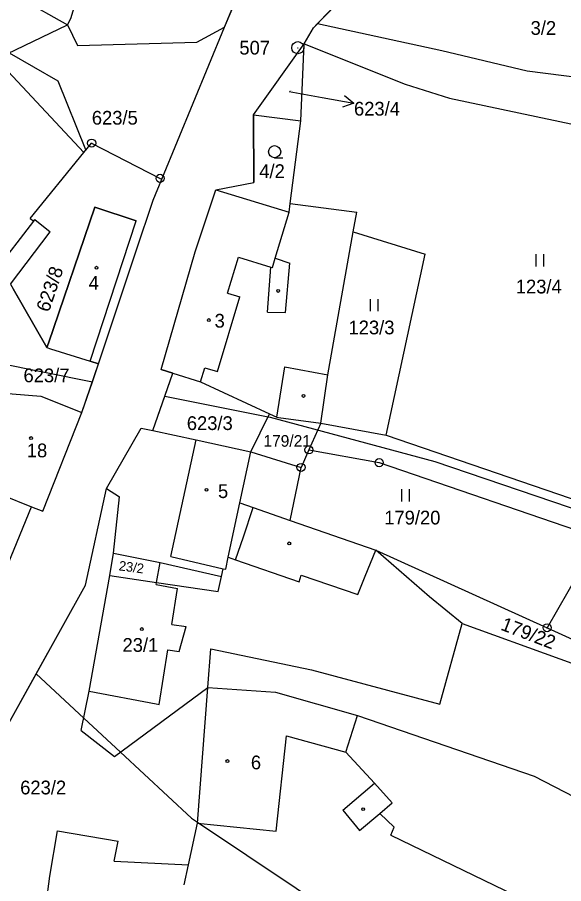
# Model space of a CAD drawing. Extents: x -743888 to -742027, y -1128394 to -1126768.
# Drawn here: x -742886 to -742818.4, y -1127432.2 to -1127325 of the extents above; entities that cross this region are included whole.
import ezdxf

# ---------------------------------------------------------------- set-up
doc = ezdxf.new("R2010")
doc.units = 0
for name, color, linetype in [('Vrstva 1', 7, 'Continuous'), ('Vrstva 16', 7, 'Continuous'), ('Vrstva 17', 7, 'Continuous'), ('Vrstva 18', 7, 'Continuous'), ('Vrstva 19', 7, 'Continuous'), ('Vrstva 24', 7, 'Continuous'), ('Vrstva 25', 7, 'Continuous'), ('Vrstva 3', 7, 'Continuous'), ('Vrstva 37', 7, 'Continuous'), ('Vrstva 4', 7, 'Continuous'), ('Vrstva 52', 7, 'Continuous'), ('Vrstva 6', 7, 'Continuous')]:
    doc.layers.add(name, color=color, linetype=linetype)

msp = doc.modelspace()

# ---------------------------------------------------------------- linework, layer by layer
at = {"layer": 'Vrstva 1'}
for points in [[(-742879.39, -1127325.18), (-742872.07, -1127300.81)], [(-742849.32, -1127326.31), (-742829.22, -1127305.6)], [(-742885.51, -1127322.69), (-742879.78, -1127325.96)], [(-742860.36, -1127326.22), (-742858.83, -1127322.61)], [(-742879.78, -1127325.96), (-742879.39, -1127325.18)], [(-742868.13, -1127345.05), (-742860.36, -1127326.22)], [(-742850.51, -1127328.29), (-742849.32, -1127326.31)], [(-742856.76, -1127337.08), (-742850.51, -1127328.29)], [(-742850.89, -1127337.85), (-742850.51, -1127328.29)], [(-742850.51, -1127328.29), (-742837.98, -1127333.31)], [(-742887.13, -1127331.73), (-742877.76, -1127341.76)], [(-742837.98, -1127333.31), (-742832.48, -1127335.04)], [(-742832.48, -1127335.04), (-742808.12, -1127340.19)], [(-742856.76, -1127337.08), (-742850.89, -1127337.85)], [(-742852.21, -1127348.07), (-742850.89, -1127337.85)], [(-742877.76, -1127341.76), (-742876.8, -1127340.59)], [(-742876.8, -1127340.59), (-742868.33, -1127344.95)], [(-742884.41, -1127349.91), (-742877.76, -1127341.76)], [(-742868.33, -1127344.95), (-742868.13, -1127345.05)], [(-742869.2, -1127347.63), (-742868.13, -1127345.05)], [(-742863.97, -1127354.06), (-742861.43, -1127346.38)], [(-742861.43, -1127346.38), (-742852.34, -1127349.14)], [(-742870.17, -1127350.6), (-742869.2, -1127347.63)], [(-742852.34, -1127349.14), (-742852.21, -1127348.07)], [(-742882.16, -1127365.36), (-742876.42, -1127348.52)], [(-742876.42, -1127348.52), (-742871.31, -1127350.22)], [(-742844.41, -1127351.58), (-742843.97, -1127349.15)], [(-742888.82, -1127356.51), (-742883.97, -1127350.26)], [(-742884.41, -1127349.91), (-742883.97, -1127350.26)], [(-742876.98, -1127367.59), (-742871.31, -1127350.22)], [(-742875.94, -1127367.92), (-742870.28, -1127350.94)], [(-742870.28, -1127350.94), (-742870.17, -1127350.6)], [(-742844.41, -1127351.58), (-742835.5, -1127354.31)], [(-742868.2, -1127368.62), (-742863.97, -1127354.06)], [(-742840.33, -1127376.73), (-742835.5, -1127354.31)], [(-742886.85, -1127358.03), (-742882.34, -1127365.88)], [(-742882.34, -1127365.88), (-742882.16, -1127365.36)], [(-742882.34, -1127365.88), (-742881.88, -1127366.03)], [(-742881.88, -1127366.03), (-742876.98, -1127367.59)], [(-742878.02, -1127373.93), (-742875.94, -1127367.92)], [(-742876.98, -1127367.59), (-742875.94, -1127367.92)], [(-742868.2, -1127368.62), (-742866.77, -1127369.06)], [(-742866.77, -1127369.06), (-742863.32, -1127370.11)], [(-742848.44, -1127375.26), (-742847.58, -1127369.27)], [(-742890.23, -1127371.33), (-742883.09, -1127371.9)], [(-742883.09, -1127371.9), (-742878.02, -1127373.93)], [(-742882.85, -1127386.15), (-742878.02, -1127373.93)], [(-742853.88, -1127374.51), (-742853.68, -1127374.54)], [(-742853.68, -1127374.54), (-742848.44, -1127375.26)], [(-742874.95, -1127383.34), (-742870.69, -1127375.86)], [(-742848.44, -1127375.26), (-742849.91, -1127378.55)], [(-742848.44, -1127375.26), (-742840.33, -1127376.73)], [(-742840.33, -1127376.73), (-742809.96, -1127387.12)], [(-742863.88, -1127377.32), (-742857.08, -1127378.78)], [(-742849.91, -1127378.55), (-742850.88, -1127380.72)], [(-742849.91, -1127378.55), (-742841.21, -1127380.13), (-742814.03, -1127389.43), (-742820.42, -1127400.56)], [(-742877.58, -1127395.3), (-742874.95, -1127383.34)], [(-742887.91, -1127384.11), (-742884.23, -1127385.59)], [(-742884.23, -1127385.59), (-742882.85, -1127386.15)], [(-742858.02, -1127389.32), (-742856.8, -1127385.69)], [(-742856.8, -1127385.69), (-742852.24, -1127387.27)], [(-742852.24, -1127387.27), (-742841.62, -1127390.96)], [(-742858.98, -1127392.15), (-742858.02, -1127389.32)], [(-742841.62, -1127390.96), (-742820.42, -1127400.56)], [(-742874.57, -1127394.1), (-742874.08, -1127391.34)], [(-742874.08, -1127391.34), (-742868.32, -1127392.49)], [(-742860.2, -1127393.33), (-742859.88, -1127391.84)], [(-742859.88, -1127391.84), (-742858.98, -1127392.15)], [(-742868.32, -1127392.49), (-742860.73, -1127394.22)], [(-742860.73, -1127394.22), (-742860.51, -1127393.26)], [(-742860.51, -1127393.26), (-742860.2, -1127393.33)], [(-742877.11, -1127408.41), (-742874.57, -1127394.1)], [(-742891.64, -1127420.53), (-742877.58, -1127395.3)], [(-742820.42, -1127400.56), (-742810.86, -1127404.89)], [(-742863.7, -1127424.73), (-742862.41, -1127407.96)], [(-742862.41, -1127407.96), (-742854.05, -1127408.52)], [(-742878.08, -1127413.29), (-742877.11, -1127408.41)], [(-742854.05, -1127408.52), (-742843.9, -1127411.41)], [(-742845.34, -1127415.94), (-742843.9, -1127411.41)], [(-742843.9, -1127411.41), (-742822, -1127418.91)], [(-742845.34, -1127415.94), (-742841.79, -1127419.79)], [(-742822, -1127418.91), (-742793.34, -1127433.72)], [(-742841.79, -1127419.79), (-742839.58, -1127422.24)], [(-742841.12, -1127423.54), (-742839.58, -1127422.24)], [(-742841.12, -1127423.54), (-742839.33, -1127425.23)], [(-742864.82, -1127429.91), (-742863.7, -1127424.73)], [(-742839.78, -1127426.23), (-742839.33, -1127425.23)], [(-742839.78, -1127426.23), (-742821.85, -1127434.87)], [(-742865.34, -1127432.36), (-742864.82, -1127429.91)]]:
    msp.add_lwpolyline(points, dxfattribs=at)
at = {"layer": 'Vrstva 16'}
msp.add_line((-742845.48, -1127334.69), (-742844.33, -1127335.66), dxfattribs=at)
for points in [[(-742852.36, -1127334.2), (-742848.27, -1127334.94)], [(-742848.27, -1127334.94), (-742844.33, -1127335.66), (-742845.75, -1127336.16)]]:
    msp.add_lwpolyline(points, dxfattribs=at)
at = {"layer": 'Vrstva 24'}
for p, q in [((-742851.33, -1127328.78), (-742851.23, -1127328.78)), ((-742876.85, -1127340.59), (-742876.75, -1127340.59)), ((-742868.38, -1127344.95), (-742868.28, -1127344.95)), ((-742849.96, -1127378.55), (-742849.86, -1127378.55)), ((-742841.26, -1127380.13), (-742841.16, -1127380.13)), ((-742850.93, -1127380.72), (-742850.83, -1127380.72)), ((-742820.47, -1127400.56), (-742820.37, -1127400.56))]:
    msp.add_line(p, q, dxfattribs=at)
for centre, radius in [((-742851.28, -1127328.78), 0.756), ((-742876.8, -1127340.59), 0.499), ((-742868.33, -1127344.95), 0.499), ((-742849.91, -1127378.55), 0.499), ((-742850.88, -1127380.72), 0.499), ((-742841.21, -1127380.13), 0.499), ((-742820.42, -1127400.56), 0.499)]:
    msp.add_circle(centre, radius, dxfattribs=at)
at = {"layer": 'Vrstva 25'}
for p, q in [((-742854.15, -1127342.4), (-742853.15, -1127342.4)), ((-742821.81, -1127354.35), (-742821.81, -1127355.85)), ((-742820.81, -1127355.85), (-742820.81, -1127354.35)), ((-742842.33, -1127359.88), (-742842.33, -1127361.38)), ((-742841.33, -1127361.38), (-742841.33, -1127359.88)), ((-742838.45, -1127383.42), (-742838.45, -1127384.92)), ((-742837.45, -1127384.92), (-742837.45, -1127383.42))]:
    msp.add_line(p, q, dxfattribs=at)
for centre, radius in [((-742854.15, -1127341.65), 0.75), ((-742876.21, -1127356.01), 0.175), ((-742853.7, -1127358.88), 0.175), ((-742862.29, -1127362.48), 0.175), ((-742850.57, -1127371.88), 0.175), ((-742884.31, -1127377.08), 0.175), ((-742862.59, -1127383.49), 0.175), ((-742852.33, -1127390.12), 0.175), ((-742870.58, -1127400.72), 0.175), ((-742860, -1127417.05), 0.175), ((-742843.18, -1127423), 0.175)]:
    msp.add_circle(centre, radius, dxfattribs=at)
at = {"layer": 'Vrstva 3'}
for points in [[(-742863.97, -1127354.06), (-742861.43, -1127346.38)], [(-742861.43, -1127346.38), (-742852.34, -1127349.14)], [(-742882.16, -1127365.36), (-742876.42, -1127348.52)], [(-742876.42, -1127348.52), (-742871.31, -1127350.22)], [(-742854.07, -1127354.83), (-742852.34, -1127349.14)], [(-742876.98, -1127367.59), (-742871.31, -1127350.22)], [(-742868.2, -1127368.62), (-742863.97, -1127354.06)], [(-742859.99, -1127359.17), (-742858.64, -1127354.7)], [(-742858.64, -1127354.7), (-742854.62, -1127355.93)], [(-742854.43, -1127355.98), (-742854.07, -1127354.83)], [(-742854.62, -1127355.93), (-742854.43, -1127355.98)], [(-742861.21, -1127368.86), (-742858.46, -1127359.63)], [(-742859.99, -1127359.17), (-742858.46, -1127359.63)], [(-742882.34, -1127365.88), (-742882.16, -1127365.36)], [(-742882.34, -1127365.88), (-742881.88, -1127366.03)], [(-742881.88, -1127366.03), (-742876.98, -1127367.59)], [(-742868.2, -1127368.62), (-742866.77, -1127369.06)], [(-742863.32, -1127370.11), (-742862.8, -1127368.38)], [(-742862.8, -1127368.38), (-742861.21, -1127368.86)], [(-742866.77, -1127369.06), (-742863.32, -1127370.11)], [(-742890.23, -1127371.33), (-742883.09, -1127371.9)], [(-742883.09, -1127371.9), (-742878.02, -1127373.93)], [(-742882.85, -1127386.15), (-742878.02, -1127373.93)], [(-742866.98, -1127391.74), (-742863.88, -1127377.32)], [(-742863.88, -1127377.32), (-742857.08, -1127378.78)], [(-742858.47, -1127385.11), (-742857.08, -1127378.78)], [(-742887.91, -1127384.11), (-742884.23, -1127385.59)], [(-742884.23, -1127385.59), (-742882.85, -1127386.15)], [(-742859.88, -1127391.84), (-742858.47, -1127385.11)], [(-742866.98, -1127391.74), (-742860.51, -1127393.26)], [(-742860.2, -1127393.33), (-742859.88, -1127391.84)], [(-742860.51, -1127393.26), (-742860.2, -1127393.33)], [(-742877.11, -1127408.41), (-742874.57, -1127394.1)], [(-742874.57, -1127394.1), (-742868.78, -1127394.95)], [(-742868.83, -1127395.2), (-742868.78, -1127394.95)], [(-742868.83, -1127395.2), (-742866.18, -1127395.7)], [(-742866.88, -1127400.14), (-742866.18, -1127395.7)], [(-742866.88, -1127400.14), (-742865.1, -1127400.42)], [(-742865.98, -1127403.51), (-742865.1, -1127400.42)], [(-742868.44, -1127410.04), (-742867.38, -1127403.29)], [(-742867.38, -1127403.29), (-742865.98, -1127403.51)], [(-742863.7, -1127424.73), (-742862.41, -1127407.96)], [(-742862.41, -1127407.96), (-742854.05, -1127408.52)], [(-742877.11, -1127408.41), (-742868.83, -1127409.96)], [(-742854.05, -1127408.52), (-742843.9, -1127411.41)], [(-742868.83, -1127409.96), (-742868.44, -1127410.04)], [(-742845.34, -1127415.94), (-742843.9, -1127411.41)], [(-742853.96, -1127425.75), (-742852.67, -1127413.92)], [(-742852.67, -1127413.92), (-742845.34, -1127415.94)], [(-742863.7, -1127424.73), (-742853.96, -1127425.75)]]:
    msp.add_lwpolyline(points, dxfattribs=at)
at = {"layer": 'Vrstva 37'}
for centre in [(-742876.21, -1127356.01), (-742862.29, -1127362.48), (-742884.31, -1127377.08), (-742862.59, -1127383.49), (-742870.58, -1127400.72), (-742860, -1127417.05)]:
    msp.add_circle(centre, 0.175, dxfattribs=at)
at = {"layer": 'Vrstva 4'}
for points in [[(-742854.07, -1127354.83), (-742852.34, -1127349.14)], [(-742883.97, -1127350.26), (-742883.82, -1127350.06)], [(-742883.82, -1127350.06), (-742881.92, -1127351.58)], [(-742886.85, -1127358.03), (-742881.92, -1127351.58)], [(-742859.99, -1127359.17), (-742858.64, -1127354.7)], [(-742858.64, -1127354.7), (-742854.62, -1127355.93)], [(-742854.43, -1127355.98), (-742854.07, -1127354.83)], [(-742854.07, -1127354.83), (-742852.28, -1127355.43)], [(-742852.82, -1127361.54), (-742852.28, -1127355.43)], [(-742855.05, -1127361.49), (-742854.62, -1127355.93)], [(-742854.62, -1127355.93), (-742854.43, -1127355.98)], [(-742861.21, -1127368.86), (-742858.46, -1127359.63)], [(-742859.99, -1127359.17), (-742858.46, -1127359.63)], [(-742855.05, -1127361.49), (-742852.82, -1127361.54)], [(-742863.32, -1127370.11), (-742862.8, -1127368.38)], [(-742862.8, -1127368.38), (-742861.21, -1127368.86)], [(-742853.88, -1127374.51), (-742852.88, -1127368.29)], [(-742852.88, -1127368.29), (-742847.58, -1127369.27)], [(-742866.98, -1127391.74), (-742863.88, -1127377.32)], [(-742858.47, -1127385.11), (-742857.08, -1127378.78)], [(-742859.88, -1127391.84), (-742858.47, -1127385.11)], [(-742858.47, -1127385.11), (-742856.8, -1127385.69)], [(-742842.93, -1127394.18), (-742841.62, -1127390.96)], [(-742866.98, -1127391.74), (-742860.51, -1127393.26)], [(-742858.98, -1127392.15), (-742851.13, -1127394.86), (-742850.85, -1127394.06), (-742843.86, -1127396.45), (-742842.93, -1127394.18)], [(-742868.78, -1127394.95), (-742868.32, -1127392.49)], [(-742868.83, -1127395.2), (-742868.78, -1127394.95)], [(-742868.83, -1127395.2), (-742866.18, -1127395.7)], [(-742866.88, -1127400.14), (-742866.18, -1127395.7)], [(-742866.88, -1127400.14), (-742865.1, -1127400.42)], [(-742865.98, -1127403.51), (-742865.1, -1127400.42)], [(-742868.44, -1127410.04), (-742867.38, -1127403.29)], [(-742867.38, -1127403.29), (-742865.98, -1127403.51)], [(-742877.11, -1127408.41), (-742868.83, -1127409.96)], [(-742868.83, -1127409.96), (-742868.44, -1127410.04)], [(-742853.96, -1127425.75), (-742852.67, -1127413.92)], [(-742852.67, -1127413.92), (-742845.34, -1127415.94)], [(-742845.71, -1127423.13), (-742841.79, -1127419.79)], [(-742845.71, -1127423.13), (-742843.66, -1127425.67)], [(-742843.66, -1127425.67), (-742841.12, -1127423.54)], [(-742863.7, -1127424.73), (-742853.96, -1127425.75)]]:
    msp.add_lwpolyline(points, dxfattribs=at)
at = {"layer": 'Vrstva 52'}
for points in [[(-742848.82, -1127325.8), (-742829.22, -1127305.6), (-742825.03, -1127301.3), (-742822.58, -1127298.79), (-742822.26, -1127298.41)], [(-742887.02, -1127329.42), (-742881, -1127332.88), (-742877.56, -1127341.38), (-742877.51, -1127341.46), (-742876.8, -1127340.59), (-742868.33, -1127344.95), (-742868.13, -1127345.05), (-742860.36, -1127326.22), (-742859.23, -1127323.55)], [(-742867.75, -1127371.9), (-742866.77, -1127369.06), (-742868.2, -1127368.62), (-742863.97, -1127354.06), (-742861.43, -1127346.38), (-742856.72, -1127345.48), (-742856.76, -1127337.08), (-742850.89, -1127337.85), (-742850.51, -1127328.29), (-742849.32, -1127326.31), (-742848.82, -1127325.8)], [(-742848.82, -1127325.8), (-742833.44, -1127329.13), (-742822.88, -1127331.63), (-742816.06, -1127332.5), (-742771.94, -1127343.13), (-742766, -1127345.25), (-742747.75, -1127350.75), (-742739.69, -1127354.5), (-742698.56, -1127368.5), (-742667.56, -1127377.88), (-742637.5, -1127385.5), (-742631.13, -1127387.63), (-742605.63, -1127394), (-742556.88, -1127403.75), (-742548.38, -1127404.63), (-742546.25, -1127405.5), (-742503, -1127408), (-742474.13, -1127407.63), (-742424.94, -1127406.75)], [(-742876.7, -1127370.12), (-742875.94, -1127367.92), (-742876.98, -1127367.59), (-742871.31, -1127350.22), (-742876.42, -1127348.52), (-742882.16, -1127365.36), (-742882.34, -1127365.88), (-742886.51, -1127358.62)], [(-742921.31, -1127357.5), (-742888.63, -1127367.75), (-742876.7, -1127370.12)], [(-742890.15, -1127399.92), (-742884.23, -1127385.59), (-742882.85, -1127386.15), (-742878.02, -1127373.93), (-742876.7, -1127370.12)], [(-742883.68, -1127406.25), (-742877.58, -1127395.3), (-742874.95, -1127383.34), (-742870.69, -1127375.86), (-742869.23, -1127376.17), (-742867.75, -1127371.9)], [(-742867.75, -1127371.9), (-742854.96, -1127374.45), (-742854.69, -1127374.5), (-742834.31, -1127380), (-742809.31, -1127388.5), (-742798.25, -1127393.13), (-742774.06, -1127401.63), (-742766.44, -1127405.5), (-742723.19, -1127420.75), (-742707.88, -1127427.13), (-742679.5, -1127436.38), (-742644.69, -1127444.5), (-742572.13, -1127460.13), (-742533.94, -1127463.63), (-742511.88, -1127465.75), (-742505.56, -1127465.75), (-742489.44, -1127467.75), (-742456.75, -1127469.5), (-742444.44, -1127470.75)], [(-742965.26, -1127573.48), (-742964.75, -1127572.6), (-742958.43, -1127564.08), (-742954.72, -1127554.49), (-742950.97, -1127547.61), (-742944.28, -1127528.98), (-742929.86, -1127490.53), (-742926.08, -1127481.57), (-742925.07, -1127479.17), (-742918.99, -1127466.07), (-742914.39, -1127456.16), (-742910.36, -1127448.54), (-742907.43, -1127444.81), (-742902.44, -1127441.06), (-742891.64, -1127420.53), (-742883.68, -1127406.25)], [(-742883.68, -1127406.25), (-742877.77, -1127411.74), (-742873.23, -1127415.96), (-742864.44, -1127424.13), (-742863.69, -1127424.62), (-742845.38, -1127436.88), (-742839.38, -1127440.25), (-742840.69, -1127443.25), (-742830.5, -1127444.88), (-742808, -1127452.13), (-742784.69, -1127456.75), (-742774.5, -1127458.88), (-742749.06, -1127465.25), (-742728.25, -1127469.5)]]:
    msp.add_lwpolyline(points, dxfattribs=at)
at = {"layer": 'Vrstva 6'}
for points in [[(-742888.34, -1127330.05), (-742879.78, -1127325.96)], [(-742879.78, -1127325.96), (-742878.56, -1127328.52)], [(-742863.79, -1127328.09), (-742860.36, -1127326.22)], [(-742878.56, -1127328.52), (-742863.79, -1127328.09)], [(-742856.76, -1127337.08), (-742856.72, -1127345.48)], [(-742861.43, -1127346.38), (-742856.72, -1127345.48)], [(-742852.21, -1127348.07), (-742843.97, -1127349.15)], [(-742847.58, -1127369.27), (-742844.41, -1127351.58)], [(-742869.23, -1127376.17), (-742866.77, -1127369.06)], [(-742863.32, -1127370.11), (-742854.79, -1127374.09)], [(-742857.08, -1127378.78), (-742854.79, -1127374.09)], [(-742854.79, -1127374.09), (-742853.88, -1127374.51)], [(-742870.69, -1127375.86), (-742869.23, -1127376.17)], [(-742869.23, -1127376.17), (-742863.88, -1127377.32)], [(-742857.08, -1127378.78), (-742850.88, -1127380.72)], [(-742852.24, -1127387.27), (-742850.88, -1127380.72)], [(-742874.95, -1127383.34), (-742873.34, -1127384.34)], [(-742874.08, -1127391.34), (-742873.34, -1127384.34)], [(-742892.14, -1127404.73), (-742884.23, -1127385.59)], [(-742834.98, -1127396.74), (-742841.62, -1127390.96)], [(-742874.57, -1127394.1), (-742868.78, -1127394.95)], [(-742861.13, -1127396.08), (-742860.73, -1127394.22)], [(-742868.78, -1127394.95), (-742861.13, -1127396.08)], [(-742830.94, -1127400.02), (-742834.98, -1127396.74)], [(-742833.68, -1127410.03), (-742830.94, -1127400.02)], [(-742830.94, -1127400.02), (-742782.56, -1127417.54)], [(-742862.41, -1127407.96), (-742862.04, -1127403.18)], [(-742862.04, -1127403.18), (-742849.6, -1127405.76)], [(-742849.6, -1127405.76), (-742833.68, -1127410.03)], [(-742873.96, -1127416.5), (-742862.41, -1127407.96)], [(-742878.08, -1127413.29), (-742873.96, -1127416.5)], [(-742881.96, -1127431.32), (-742881.02, -1127425.68)], [(-742881.02, -1127425.68), (-742873.52, -1127426.98)], [(-742874, -1127429.43), (-742873.52, -1127426.98)], [(-742874, -1127429.43), (-742864.82, -1127429.91)], [(-742882.42, -1127434.76), (-742881.96, -1127431.32)]]:
    msp.add_lwpolyline(points, dxfattribs=at)

# ---------------------------------------------------------------- texts
at = {"layer": 'Vrstva 16'}
msp.add_text('623/4', height=1.7, dxfattribs=at).set_placement((-742844.32, -1127337.18))
at = {"layer": 'Vrstva 17'}
msp.add_text('507', height=1.7, dxfattribs=at).set_placement((-742858.51, -1127329.63))
at = {"layer": 'Vrstva 18'}
for s, height, p in [('3/2', 1.7, (-742822.46, -1127327.19)), ('623/4', 0.1, (-742852.36, -1127334.2)), ('623/5', 1.7, (-742876.78, -1127338.3)), ('4/2', 1.7, (-742856.05, -1127344.91)), ('123/4', 1.7, (-742824.29, -1127359.19)), ('123/3', 1.7, (-742845, -1127364.25)), ('623/7', 1.7, (-742885.24, -1127370.18)), ('623/3', 1.7, (-742865.02, -1127376.09)), ('179/21', 1.44, (-742855.54, -1127378.16)), ('179/20', 1.7, (-742840.58, -1127387.78)), ('623/2', 1.7, (-742885.65, -1127421.18))]:
    msp.add_text(s, height=height, dxfattribs=at).set_placement(p)
for s, rotation, p in [('623/8', 71.3011, (-742882.1, -1127361.6)), ('179/22', 339.0443, (-742826.27, -1127400.78))]:
    msp.add_text(s, height=1.7, rotation=rotation, dxfattribs=at).set_placement(p)
at = {"layer": 'Vrstva 19'}
for s, p in [('4', (-742877.17, -1127358.72)), ('3', (-742861.58, -1127363.42)), ('18', (-742884.83, -1127379.47)), ('5', (-742861.16, -1127384.51)), ('23/1', (-742872.98, -1127403.54)), ('6', (-742857.09, -1127418.08))]:
    msp.add_text(s, height=1.7, dxfattribs=at).set_placement(p)
msp.add_text('23/2', height=1.19, rotation=352.6374, dxfattribs=at).set_placement((-742873.49, -1127393.45))

doc.saveas('drawing.dxf')
